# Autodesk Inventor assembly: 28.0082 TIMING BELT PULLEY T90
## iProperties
Created: 2007-04
Part Number: 28.0082 TIMING BELT PULLEY T90
Document SubType Name: Assembly
Designer: Andy Moles
Author: Andy Moles
